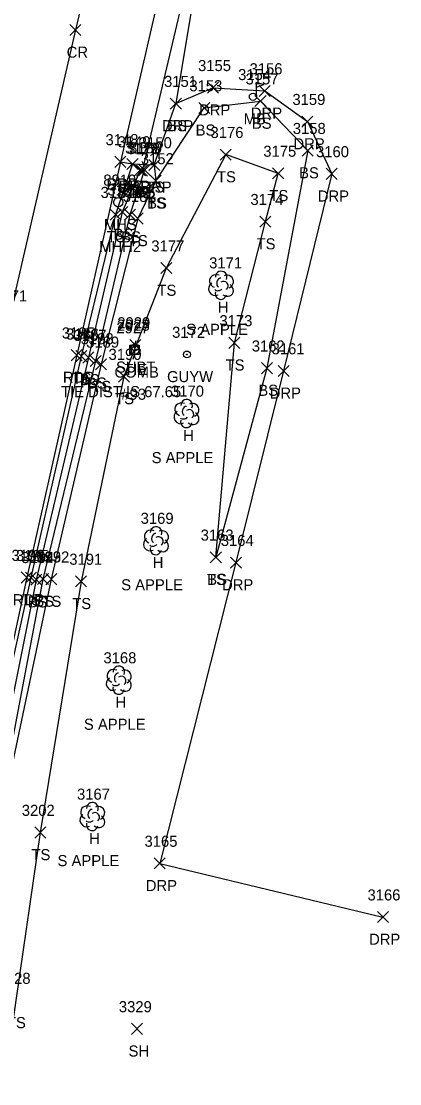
# Model space of a CAD drawing. Extents: x 1678863 to 1683592, y 407783 to 418211.
# Drawn here: x 1680444.6 to 1680513, y 414913.1 to 415105 of the extents above; entities that cross this region are included whole.
import ezdxf

# ---------------------------------------------------------------- set-up
doc = ezdxf.new("R2010")
doc.units = 0
for name, color, linetype in [('C_A', 7, 'Continuous'), ('C_C', 7, 'Continuous'), ('C_I', 7, 'Continuous'), ('CBP', 7, 'Continuous'), ('D_A', 7, 'Continuous'), ('D_I', 7, 'Continuous'), ('D_TIC', 7, 'Continuous'), ('DCP', 7, 'Continuous'), ('L_A', 7, 'Continuous'), ('L_C', 7, 'Continuous'), ('L_I', 7, 'Continuous'), ('L_TIC', 7, 'Continuous'), ('LELB', 7, 'Continuous'), ('LMB', 7, 'Continuous'), ('LTD', 7, 'Continuous'), ('P_A', 7, 'Continuous'), ('P_I', 7, 'Continuous'), ('P_TIC', 7, 'Continuous'), ('PET', 7, 'Continuous'), ('PRC', 7, 'Continuous'), ('R_A', 7, 'Continuous'), ('R_I', 7, 'Continuous'), ('R_TIC', 7, 'Continuous'), ('RDP', 7, 'Continuous'), ('U_A', 7, 'Continuous'), ('U_C', 7, 'Continuous'), ('U_I', 7, 'Continuous'), ('U_TIC', 7, 'Continuous'), ('UP', 7, 'Continuous'), ('UPGW', 7, 'Continuous'), ('USMH', 7, 'Continuous')]:
    doc.layers.add(name, color=color, linetype=linetype)

msp = doc.modelspace()

# ---------------------------------------------------------------- linework, layer by layer
at = {"layer": 'CBP'}
for radius in [0.625, 0.0833]:
    msp.add_circle((1680465.19, 415046.1), radius, dxfattribs=at)
at = {"layer": 'D_TIC'}
for points in [[(1680465.49, 415076.97), (1680467.49, 415078.97)], [(1680467.49, 415076.97), (1680465.49, 415078.97)]]:
    msp.add_lwpolyline(points, dxfattribs=at)
at = {"layer": 'DCP'}
msp.add_lwpolyline([(1680487.21, 415165.67), (1680466.49, 415077.97)], dxfattribs=at)
at = {"layer": 'L_TIC'}
for points in [[(1680471.59, 415089.11), (1680473.59, 415091.11)], [(1680473.59, 415089.11), (1680471.59, 415091.11)], [(1680476.72, 415088.32), (1680478.72, 415090.32)], [(1680478.72, 415088.32), (1680476.72, 415090.32)], [(1680486.88, 415089.56), (1680488.88, 415091.56)], [(1680488.88, 415089.56), (1680486.88, 415091.56)], [(1680495.42, 415080.61), (1680497.42, 415082.61)], [(1680497.42, 415080.61), (1680495.42, 415082.61)], [(1680480.61, 415079.89), (1680482.61, 415081.89)], [(1680482.61, 415079.89), (1680480.61, 415081.89)], [(1680463.76, 415078.21), (1680465.76, 415080.21)], [(1680465.76, 415078.21), (1680463.76, 415080.21)], [(1680465.13, 415077.06), (1680467.13, 415079.06)], [(1680467.13, 415077.06), (1680465.13, 415079.06)], [(1680465.13, 415077.06), (1680467.13, 415079.06)], [(1680467.13, 415077.06), (1680465.13, 415079.06)], [(1680465.92, 415077.12), (1680467.92, 415079.12)], [(1680467.92, 415077.12), (1680465.92, 415079.12)], [(1680467.69, 415078.03), (1680469.69, 415080.03)], [(1680469.69, 415078.03), (1680467.69, 415080.03)], [(1680467.96, 415075.15), (1680469.96, 415077.15)], [(1680469.96, 415075.15), (1680467.96, 415077.15)], [(1680467.96, 415075.15), (1680469.96, 415077.15)], [(1680469.96, 415075.15), (1680467.96, 415077.15)], [(1680490.08, 415076.5), (1680492.08, 415078.5)], [(1680492.08, 415076.5), (1680490.08, 415078.5)], [(1680460.69, 415069.07), (1680462.69, 415071.07)], [(1680462.69, 415069.07), (1680460.69, 415071.07)], [(1680461.9, 415069.52), (1680463.9, 415071.52)], [(1680463.9, 415069.52), (1680461.9, 415071.52)], [(1680463.28, 415069.04), (1680465.28, 415071.04)], [(1680465.28, 415069.04), (1680463.28, 415071.04)], [(1680464.69, 415068.36), (1680466.69, 415070.36)], [(1680466.69, 415068.36), (1680464.69, 415070.36)], [(1680487.77, 415067.79), (1680489.77, 415069.79)], [(1680489.77, 415067.79), (1680487.77, 415069.79)], [(1680469.85, 415059.4), (1680471.85, 415061.4)], [(1680471.85, 415059.4), (1680469.85, 415061.4)], [(1680482.17, 415045.91), (1680484.17, 415047.91)], [(1680484.17, 415045.91), (1680482.17, 415047.91)], [(1680454.5, 415043.5), (1680456.5, 415045.5)], [(1680456.5, 415043.5), (1680454.5, 415045.5)], [(1680455.79, 415043.26), (1680457.79, 415045.26)], [(1680457.79, 415043.26), (1680455.79, 415045.26)], [(1680457.08, 415042.65), (1680459.08, 415044.65)], [(1680459.08, 415042.65), (1680457.08, 415044.65)], [(1680458.08, 415042.04), (1680460.08, 415044.04)], [(1680460.08, 415042.04), (1680458.08, 415044.04)], [(1680488.05, 415041.34), (1680490.05, 415043.34)], [(1680490.05, 415041.34), (1680488.05, 415043.34)], [(1680462.21, 415039.83), (1680464.21, 415041.83)], [(1680464.21, 415039.83), (1680462.21, 415041.83)], [(1680478.81, 415007.2), (1680480.81, 415009.2)], [(1680480.81, 415007.2), (1680478.81, 415009.2)], [(1680478.81, 415007.2), (1680480.81, 415009.2)], [(1680480.81, 415007.2), (1680478.81, 415009.2)], [(1680445.4, 415003.52), (1680447.4, 415005.52)], [(1680447.4, 415003.52), (1680445.4, 415005.52)], [(1680446.37, 415003.15), (1680448.37, 415005.15)], [(1680448.37, 415003.15), (1680446.37, 415005.15)], [(1680447.58, 415003.27), (1680449.58, 415005.27)], [(1680449.58, 415003.27), (1680447.58, 415005.27)], [(1680449.07, 415003.25), (1680451.07, 415005.25)], [(1680451.07, 415003.25), (1680449.07, 415005.25)], [(1680454.46, 415002.84), (1680456.46, 415004.84)], [(1680456.46, 415002.84), (1680454.46, 415004.84)], [(1680447.09, 414957.51), (1680449.09, 414959.51)], [(1680449.09, 414957.51), (1680447.09, 414959.51)], [(1680464.56, 414922.06), (1680466.56, 414924.06)], [(1680466.56, 414922.06), (1680464.56, 414924.06)]]:
    msp.add_lwpolyline(points, dxfattribs=at)
at = {"layer": 'LELB'}
for points in [[(1680482.81, 415138.08), (1680477.17, 415117.67), (1680472.59, 415090.11)], [(1680468.96, 415076.15), (1680477.72, 415089.32), (1680487.88, 415090.56), (1680496.42, 415081.61), (1680489.05, 415042.34), (1680479.81, 415008.2)], [(1680479.81, 415008.2), (1680483.17, 415046.91), (1680488.77, 415068.79), (1680491.08, 415077.5), (1680481.61, 415080.89), (1680470.85, 415060.4), (1680463.21, 415040.83), (1680455.46, 415003.84), (1680448.09, 414958.51), (1680443.65, 414928.18), (1680439.14, 414897.3), (1680440.11, 414863.23)], [(1680468.69, 415079.03), (1680468.96, 415076.15), (1680465.69, 415069.36), (1680459.08, 415043.04), (1680450.07, 415004.25), (1680441.01, 414961.34), (1680435.8, 414931.59), (1680430.09, 414897.33), (1680426.27, 414867.42)], [(1680464.76, 415079.21), (1680461.69, 415070.07), (1680455.5, 415044.5), (1680446.4, 415004.52), (1680437.05, 414962.28), (1680431.37, 414933.29), (1680427.85, 414897.38)], [(1680466.13, 415078.06), (1680462.9, 415070.52), (1680456.79, 415044.26), (1680447.37, 415004.15), (1680438.85, 414961.95), (1680432.35, 414932.78), (1680427.85, 414897.38), (1680422.35, 414868.61), (1680417.81, 414844.43)], [(1680466.13, 415078.06), (1680466.92, 415078.12), (1680464.28, 415070.04), (1680458.08, 415043.65), (1680448.58, 415004.27), (1680440.36, 414961.31), (1680433.46, 414932.58), (1680427.85, 414897.38)]]:
    msp.add_lwpolyline(points, dxfattribs=at)
at = {"layer": 'LMB'}
for p, q in [((1680487.19, 415091.35), (1680487.18, 415093.95)), ((1680487.18, 415093.94), (1680488.47, 415093.56)), ((1680487.18, 415093.05), (1680488.47, 415093.55)), ((1680486.53, 415091.34), (1680486.53, 415091.34))]:
    msp.add_line(p, q, dxfattribs=at)
msp.add_circle((1680486.53, 415091.34), 0.656, dxfattribs=at)
at = {"layer": 'LTD'}
for p, q in [((1680480.73, 415057.35), (1680480.73, 415057.35)), ((1680480.73, 415057.35), (1680480.73, 415057.35)), ((1680474.49, 415034.19), (1680474.49, 415034.19)), ((1680474.49, 415034.19), (1680474.49, 415034.19)), ((1680468.98, 415011.23), (1680468.98, 415011.23)), ((1680468.98, 415011.23), (1680468.98, 415011.23)), ((1680462.25, 414986.05), (1680462.25, 414986.05)), ((1680462.25, 414986.05), (1680462.25, 414986.05)), ((1680457.47, 414961.43), (1680457.47, 414961.43)), ((1680457.47, 414961.43), (1680457.47, 414961.43))]:
    msp.add_line(p, q, dxfattribs=at)
for centre in [(1680480.78, 415058.79), (1680474.53, 415035.63), (1680469.02, 415012.67), (1680462.29, 414987.49), (1680457.52, 414962.87)]:
    msp.add_arc(centre, 1.05, 335.5272, 180.9563, dxfattribs=at)
for centre, major_axis, ratio, start_param, end_param in [((1680479.94, 415058.02), (1.21, -0.51), 0.895232, 1.570796, 4.712389), ((1680479.65, 415056.64), (0.58, -1.04), 0.959034, 3.141593, 6.283185), ((1680480.52, 415057.81), (-0.208, -0.792), 0.645439, 3.141593, 6.283185), ((1680481.23, 415057.19), (-0.5, 0.667), 0.989748, 3.141593, 6.283185), ((1680481.73, 415056.52), (-1.09, 0.79), 0.841452, 1.570796, 4.712389), ((1680481.77, 415057.94), (-1.14, -0.48), 0.949671, 1.570796, 4.712389), ((1680480.73, 415055.85), (0.26, 1.06), 0.942809, 1.570796, 4.712389), ((1680480.27, 415056.6), (-0.625, -0.083), 0.423636, 0, 3.141593), ((1680473.4, 415033.48), (0.58, -1.04), 0.959034, 3.141593, 6.283185), ((1680473.7, 415034.86), (1.21, -0.51), 0.895232, 1.570796, 4.712389), ((1680474.28, 415034.65), (-0.208, -0.792), 0.645439, 3.141593, 6.283185), ((1680474.99, 415034.03), (-0.5, 0.667), 0.989748, 3.141593, 6.283185), ((1680475.53, 415034.78), (-1.14, -0.48), 0.949671, 1.570796, 4.712389), ((1680474.49, 415032.69), (0.26, 1.06), 0.942809, 1.570796, 4.712389), ((1680474.03, 415033.44), (-0.625, -0.083), 0.423636, 0, 3.141593), ((1680475.49, 415033.36), (-1.09, 0.79), 0.841452, 1.570796, 4.712389), ((1680467.89, 415010.52), (0.58, -1.04), 0.959034, 3.141593, 6.283185), ((1680468.19, 415011.9), (1.21, -0.51), 0.895232, 1.570796, 4.712389), ((1680468.77, 415011.69), (-0.208, -0.792), 0.645439, 3.141593, 6.283185), ((1680469.48, 415011.07), (-0.5, 0.667), 0.989748, 3.141593, 6.283185), ((1680470.02, 415011.82), (-1.14, -0.48), 0.949671, 1.570796, 4.712389), ((1680468.98, 415009.73), (0.26, 1.06), 0.942809, 1.570796, 4.712389), ((1680468.52, 415010.48), (-0.625, -0.083), 0.423636, 0, 3.141593), ((1680469.98, 415010.4), (-1.09, 0.79), 0.841452, 1.570796, 4.712389), ((1680461.46, 414986.72), (1.21, -0.51), 0.895232, 1.570796, 4.712389), ((1680462.04, 414986.51), (-0.208, -0.792), 0.645439, 3.141593, 6.283185), ((1680462.75, 414985.89), (-0.5, 0.667), 0.989748, 3.141593, 6.283185), ((1680463.29, 414986.64), (-1.14, -0.48), 0.949671, 1.570796, 4.712389), ((1680461.16, 414985.35), (0.58, -1.04), 0.959034, 3.141593, 6.283185), ((1680462.25, 414984.55), (0.26, 1.06), 0.942809, 1.570796, 4.712389), ((1680461.79, 414985.3), (-0.625, -0.083), 0.423636, 0, 3.141593), ((1680463.25, 414985.22), (-1.09, 0.79), 0.841452, 1.570796, 4.712389), ((1680456.68, 414962.1), (1.21, -0.51), 0.895232, 1.570796, 4.712389), ((1680456.39, 414960.72), (0.58, -1.04), 0.959034, 3.141593, 6.283185), ((1680457.26, 414961.89), (-0.208, -0.792), 0.645439, 3.141593, 6.283185), ((1680457.97, 414961.27), (-0.5, 0.667), 0.989748, 3.141593, 6.283185), ((1680458.51, 414962.02), (-1.14, -0.48), 0.949671, 1.570796, 4.712389), ((1680457.47, 414959.93), (0.26, 1.06), 0.942809, 1.570796, 4.712389), ((1680457.01, 414960.68), (-0.625, -0.083), 0.423636, 0, 3.141593), ((1680458.47, 414960.6), (-1.09, 0.79), 0.841452, 1.570796, 4.712389)]:
    msp.add_ellipse(centre, major_axis=major_axis, ratio=ratio, start_param=start_param, end_param=end_param, dxfattribs=at)
at = {"layer": 'P_TIC'}
for points in [[(1680453.43, 415102.39), (1680455.43, 415104.39)], [(1680455.43, 415102.39), (1680453.43, 415104.39)], [(1680461.57, 415078.59), (1680463.57, 415080.59)], [(1680463.57, 415078.59), (1680461.57, 415080.59)], [(1680453.69, 415043.69), (1680455.69, 415045.69)], [(1680455.69, 415043.69), (1680453.69, 415045.69)], [(1680444.65, 415003.54), (1680446.65, 415005.54)], [(1680446.65, 415003.54), (1680444.65, 415005.54)]]:
    msp.add_lwpolyline(points, dxfattribs=at)
at = {"layer": 'PET'}
msp.add_lwpolyline([(1680495.8, 415211.55), (1680487.74, 415180.8), (1680478.66, 415148.16), (1680471.94, 415120.07), (1680462.57, 415079.59), (1680454.69, 415044.69), (1680445.65, 415004.54), (1680436.54, 414962.49), (1680430.18, 414933.71), (1680423.61, 414897.47), (1680418.44, 414869.8), (1680415.44, 414847.01), (1680410.82, 414817.35), (1680406.85, 414787.83), (1680404.02, 414758.7), (1680400.52, 414722.33), (1680395.79, 414677.26), (1680393.31, 414652.78), (1680390.17, 414616.43), (1680385.57, 414569.94), (1680383.24, 414550.06), (1680381.08, 414523.52), (1680377.37, 414484.42)], dxfattribs=at)
at = {"layer": 'PRC'}
msp.add_lwpolyline([(1680481.59, 415211.17), (1680473.06, 415178.67), (1680464.71, 415146.4), (1680454.43, 415103.39), (1680442.46, 415051.38), (1680433.87, 415013.05), (1680427.71, 414986.46), (1680420.88, 414953.3), (1680415, 414925.91), (1680408.48, 414889.99), (1680403.43, 414856.87), (1680399.05, 414826.29), (1680394.79, 414790.7), (1680390.07, 414747.8), (1680385.23, 414697.92), (1680381.06, 414656.38), (1680376.28, 414606.57), (1680371.5, 414556.43), (1680367.38, 414511.69), (1680362.63, 414458.59)], dxfattribs=at)
at = {"layer": 'R_TIC'}
for points in [[(1680478.29, 415091.97), (1680480.29, 415093.97)], [(1680480.29, 415091.97), (1680478.29, 415093.97)], [(1680487.66, 415091.39), (1680489.66, 415093.39)], [(1680489.66, 415091.39), (1680487.66, 415093.39)], [(1680471.59, 415089.11), (1680473.59, 415091.11)], [(1680473.59, 415089.11), (1680471.59, 415091.11)], [(1680495.35, 415085.85), (1680497.35, 415087.85)], [(1680497.35, 415085.85), (1680495.35, 415087.85)], [(1680461.57, 415078.59), (1680463.57, 415080.59)], [(1680463.57, 415078.59), (1680461.57, 415080.59)], [(1680463.76, 415078.21), (1680465.76, 415080.21)], [(1680465.76, 415078.21), (1680463.76, 415080.21)], [(1680467.69, 415078.03), (1680469.69, 415080.03)], [(1680469.69, 415078.03), (1680467.69, 415080.03)], [(1680499.75, 415076.42), (1680501.75, 415078.42)], [(1680501.75, 415076.42), (1680499.75, 415078.42)], [(1680491.06, 415040.84), (1680493.06, 415042.84)], [(1680493.06, 415040.84), (1680491.06, 415042.84)], [(1680482.45, 415006.24), (1680484.45, 415008.24)], [(1680484.45, 415006.24), (1680482.45, 415008.24)], [(1680468.67, 414951.93), (1680470.67, 414953.93)], [(1680470.67, 414951.93), (1680468.67, 414953.93)], [(1680509.01, 414942.24), (1680511.01, 414944.24)], [(1680511.01, 414942.24), (1680509.01, 414944.24)]]:
    msp.add_lwpolyline(points, dxfattribs=at)
at = {"layer": 'RDP'}
msp.add_lwpolyline([(1680462.57, 415079.59), (1680464.76, 415079.21), (1680468.69, 415079.03), (1680472.59, 415090.11), (1680479.29, 415092.97), (1680488.66, 415092.39), (1680496.35, 415086.85), (1680500.75, 415077.42), (1680492.06, 415041.84), (1680483.45, 415007.24), (1680469.67, 414952.93), (1680510.01, 414943.24)], dxfattribs=at)
at = {"layer": 'U_TIC'}
for points in [[(1680464.27, 415045.54), (1680466.27, 415047.54)], [(1680466.27, 415045.54), (1680464.27, 415047.54)]]:
    msp.add_lwpolyline(points, dxfattribs=at)
at = {"layer": 'UP'}
for p, q in [((1680464.27, 415044.79), (1680464.27, 415046.46)), ((1680464.27, 415046.46), (1680465.94, 415046.46)), ((1680465.35, 415047.29), (1680465.1, 415046.46)), ((1680465.94, 415046.46), (1680465.94, 415044.79)), ((1680465.94, 415044.79), (1680464.27, 415044.79)), ((1680464.85, 415043.96), (1680465.1, 415044.79)), ((1680465.1, 415045.63), (1680465.1, 415045.63))]:
    msp.add_line(p, q, dxfattribs=at)
msp.add_circle((1680465.1, 415045.63), 0.833, dxfattribs=at)
at = {"layer": 'UPGW'}
for radius in [0.625, 0.0833]:
    msp.add_circle((1680474.6, 415044.81), radius, dxfattribs=at)
at = {"layer": 'USMH'}
for p, q in [((1680462.18, 415072.29), (1680462.18, 415072.29)), ((1680463.01, 415072.29), (1680463.01, 415072.29))]:
    msp.add_line(p, q, dxfattribs=at)
msp.add_circle((1680462.18, 415072.29), 0.833, dxfattribs=at)

# ---------------------------------------------------------------- texts
at = {"layer": 'C_A'}
msp.add_text('TIE', height=2, dxfattribs=at).set_placement((1680463.27, 415041.1))
at = {"layer": 'C_C'}
msp.add_text('TIE DIST IS 67.65', height=2, dxfattribs=at).set_placement((1680451.85, 415037.1))
at = {"layer": 'C_I'}
msp.add_text('2928', height=2, dxfattribs=at).set_placement((1680461.93, 415049.1))
at = {"layer": 'D_A'}
msp.add_text('P', height=2, dxfattribs=at).set_placement((1680465.87, 415072.97))
at = {"layer": 'D_I'}
msp.add_text('3178', height=2, dxfattribs=at).set_placement((1680463.8, 415080.97))
at = {"layer": 'L_A'}
for s, p in [('MB', (1680484.84, 415086.34)), ('BS', (1680471.03, 415085.11)), ('BS', (1680476.16, 415084.32)), ('BS', (1680486.32, 415085.56)), ('BS', (1680494.86, 415076.61)), ('TS', (1680480.02, 415075.89)), ('TS', (1680463.17, 415074.21)), ('BS', (1680464.57, 415073.06)), ('BS', (1680464.57, 415073.06)), ('BS', (1680465.36, 415073.12)), ('TS', (1680467.1, 415074.03)), ('TS', (1680467.37, 415071.15)), ('BS', (1680467.4, 415071.15)), ('TS', (1680489.49, 415072.5)), ('TS', (1680460.1, 415065.07)), ('BS', (1680461.34, 415065.52)), ('BS', (1680462.72, 415065.04)), ('TS', (1680464.1, 415064.36)), ('TS', (1680487.18, 415063.79)), ('TS', (1680469.26, 415055.4)), ('H', (1680480.16, 415052.35)), ('TS', (1680481.58, 415041.91)), ('TS', (1680453.91, 415039.5)), ('BS', (1680455.23, 415039.26)), ('BS', (1680456.52, 415038.65)), ('TS', (1680457.49, 415038.04)), ('BS', (1680487.49, 415037.34)), ('TS', (1680461.62, 415035.83)), ('H', (1680473.92, 415029.19)), ('H', (1680468.41, 415006.23)), ('TS', (1680478.22, 415003.2)), ('BS', (1680478.25, 415003.2)), ('TS', (1680444.81, 414999.52)), ('BS', (1680445.81, 414999.15)), ('BS', (1680447.02, 414999.27)), ('TS', (1680448.48, 414999.25)), ('TS', (1680453.87, 414998.84)), ('H', (1680461.68, 414981.05)), ('H', (1680456.91, 414956.43)), ('TS', (1680446.5, 414953.51)), ('TS', (1680442.06, 414923.18)), ('SH', (1680464.04, 414918.06))]:
    msp.add_text(s, height=2, dxfattribs=at).set_placement(p)
at = {"layer": 'L_C'}
for p in [(1680474.46, 415048.35), (1680468.22, 415025.19), (1680462.71, 415002.23), (1680455.98, 414977.05), (1680451.21, 414952.43)]:
    msp.add_text('S APPLE', height=2, dxfattribs=at).set_placement(p)
at = {"layer": 'L_I'}
for s, p in [('3154', (1680483.84, 415094.34)), ('3151', (1680470.46, 415093.11)), ('3153', (1680475.03, 415092.32)), ('3157', (1680485.18, 415093.56)), ('3158', (1680493.72, 415084.61)), ('3176', (1680478.86, 415083.89)), ('3149', (1680462.06, 415082.21)), ('3179', (1680463.43, 415081.06)), ('3179', (1680463.43, 415081.06)), ('3180', (1680464.14, 415081.12)), ('3150', (1680465.91, 415082.03)), ('3175', (1680488.39, 415080.5)), ('3152', (1680466.26, 415079.15)), ('3152', (1680466.26, 415079.15)), ('3184', (1680458.99, 415073.07)), ('3183', (1680460.2, 415073.52)), ('3181', (1680462.15, 415073.04)), ('3182', (1680462.99, 415072.36)), ('3174', (1680486.07, 415071.79)), ('3177', (1680468.16, 415063.4)), ('3171', (1680478.6, 415060.35)), ('3173', (1680480.47, 415049.91)), ('3186', (1680452.75, 415047.5)), ('3187', (1680454.1, 415047.26)), ('3188', (1680455.39, 415046.65)), ('3189', (1680456.38, 415046.04)), ('3162', (1680486.31, 415045.34)), ('3190', (1680460.43, 415043.83)), ('3170', (1680471.71, 415037.19)), ('3169', (1680466.23, 415014.23)), ('3163', (1680477.07, 415011.2)), ('3163', (1680477.07, 415011.2)), ('3195', (1680443.71, 415007.52)), ('3194', (1680444.67, 415007.15)), ('3193', (1680445.89, 415007.27)), ('3192', (1680447.38, 415007.25)), ('3191', (1680453.33, 415006.84)), ('3168', (1680459.51, 414989.05)), ('3167', (1680454.73, 414964.43)), ('3202', (1680444.75, 414961.51)), ('3328', (1680440.39, 414931.18)), ('3329', (1680462.29, 414926.06))]:
    msp.add_text(s, height=2, dxfattribs=at).set_placement(p)
at = {"layer": 'P_A'}
for s, p in [('CR', (1680452.86, 415098.39)), ('RDP', (1680460.06, 415074.59)), ('RDP', (1680452.18, 415039.69)), ('RDP', (1680443.14, 414999.54))]:
    msp.add_text(s, height=2, dxfattribs=at).set_placement(p)
at = {"layer": 'P_I'}
for s, p in [('3148', (1680459.88, 415082.59)), ('2871', (1680439.77, 415054.38)), ('3185', (1680451.99, 415047.69)), ('3196', (1680442.9, 415007.54))]:
    msp.add_text(s, height=2, dxfattribs=at).set_placement(p)
at = {"layer": 'R_A'}
for p in [(1680476.78, 415087.97), (1680486.15, 415087.39), (1680470.08, 415085.11), (1680493.84, 415081.85), (1680460.06, 415074.59), (1680462.25, 415074.21), (1680466.18, 415074.03), (1680498.24, 415072.42), (1680489.55, 415036.84), (1680480.94, 415002.24), (1680467.16, 414947.93), (1680507.5, 414938.24)]:
    msp.add_text('DRP', height=2, dxfattribs=at).set_placement(p)
at = {"layer": 'R_I'}
for s, p in [('3155', (1680476.6, 415095.97)), ('3156', (1680485.91, 415095.39)), ('3151', (1680470.46, 415093.11)), ('3159', (1680493.65, 415089.85)), ('3148', (1680459.88, 415082.59)), ('3149', (1680462.06, 415082.21)), ('3150', (1680465.91, 415082.03)), ('3160', (1680497.92, 415080.42)), ('3161', (1680489.89, 415044.84)), ('3164', (1680480.71, 415010.24)), ('3165', (1680466.93, 414955.93)), ('3166', (1680507.22, 414946.24))]:
    msp.add_text(s, height=2, dxfattribs=at).set_placement(p)
at = {"layer": 'U_A'}
for s, p in [('MHS', (1680459.59, 415067.29)), ('COMB', (1680461.49, 415040.63)), ('SUBT', (1680461.77, 415041.54)), ('GUYW', (1680471, 415039.81))]:
    msp.add_text(s, height=2, dxfattribs=at).set_placement(p)
at = {"layer": 'U_C'}
for s, p in [('MHH2', (1680458.74, 415063.29)), ('#93', (1680462.74, 415036.63))]:
    msp.add_text(s, height=2, dxfattribs=at).set_placement(p)
at = {"layer": 'U_I'}
for s, p in [('8919', (1680459.48, 415075.29)), ('2927', (1680461.84, 415048.63)), ('2929', (1680462.01, 415049.54)), ('3172', (1680471.91, 415047.81))]:
    msp.add_text(s, height=2, dxfattribs=at).set_placement(p)

doc.saveas('drawing.dxf')
